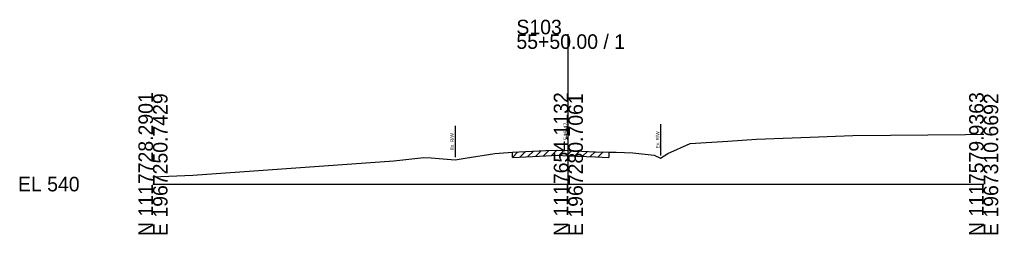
# Model space of a CAD drawing. Extents: x -26 to 163, y -10 to 24018.
# Drawn here: x -25.7 to 162.8, y 4990.3 to 5031.7 of the extents above; entities that cross this region are included whole.
import ezdxf

# ---------------------------------------------------------------- set-up
doc = ezdxf.new("R2010")
doc.units = 0
for name, color, linetype in [('RD_GPK_XS_Cell', 7, 'Continuous'), ('RD_XS_ExGround', 7, 'Continuous'), ('RD_XS_ExPaveRet', 7, 'Continuous'), ('RD_XS_ExRW', 7, 'Continuous'), ('RD_XS_TX_Elev_EX', 7, 'Continuous')]:
    doc.layers.add(name, color=color, linetype=linetype)

msp = doc.modelspace()

# ---------------------------------------------------------------- linework, layer by layer
at = {"layer": 'RD_GPK_XS_Cell'}
for p, q in [((80, 5000), (80, 5028.84)), ((0, 5000), (80, 5000)), ((80, 5000), (160, 5000))]:
    msp.add_line(p, q, dxfattribs=at)
at = {"layer": 'RD_XS_ExGround'}
msp.add_lwpolyline([(0, 5001.42), (7.7, 5001.74), (23.01, 5002.81), (46.41, 5004.49), (52.19, 5005.15), (53.59, 5005.06), (58.18, 5004.69), (60.16, 5005.02), (65.84, 5005.86), (66.67, 5005.94), (69.23, 5006.15), (75.68, 5006.46), (77.87, 5006.56), (80, 5006.47), (85.26, 5006.23), (87.77, 5006.15), (89.22, 5006.12), (92.43, 5005.99), (96.52, 5005.54), (97.78, 5005.01), (99.16, 5005.87), (103.45, 5007.83), (110.74, 5008.28), (116.23, 5008.66), (126.52, 5009.04), (134.83, 5009.36), (156.52, 5009.55), (159.34, 5009.61), (160, 5009.58)], dxfattribs=at)
at = {"layer": 'RD_XS_ExPaveRet'}
for p, q in [((69.23, 5005.15), (70.28, 5006.2)), ((69.23, 5005.15), (69.23, 5006.15)), ((70.73, 5005.22), (71.78, 5006.27)), ((72.23, 5005.29), (73.28, 5006.35)), ((73.73, 5005.37), (74.78, 5006.42)), ((75.23, 5005.44), (76.27, 5006.49)), ((75.68, 5005.46), (77.87, 5005.56)), ((76.73, 5005.51), (77.77, 5006.56)), ((77.87, 5005.56), (80, 5005.47)), ((78.23, 5005.55), (79.18, 5006.5)), ((79.73, 5005.48), (80.68, 5006.44)), ((81.23, 5005.41), (82.18, 5006.37)), ((82.73, 5005.35), (83.68, 5006.3)), ((84.23, 5005.28), (85.18, 5006.24)), ((85.73, 5005.22), (86.69, 5006.19)), ((87.77, 5006.15), (87.77, 5005.15)), ((69.23, 5005.15), (75.68, 5005.46)), ((80, 5005.47), (85.26, 5005.23)), ((85.26, 5005.23), (87.77, 5005.15))]:
    msp.add_line(p, q, dxfattribs=at)
at = {"layer": 'RD_XS_ExRW'}
for p, q in [((97.78, 5011.51), (97.78, 5005.51)), ((58.18, 5011.19), (58.18, 5005.19))]:
    msp.add_line(p, q, dxfattribs=at)

# ---------------------------------------------------------------- texts
at = {"layer": 'RD_GPK_XS_Cell'}
for s, p in [('S103', (70, 5028.84)), ('55+50.00 / 1', (70, 5026.04)), ('EL 540', (-26, 4998.6))]:
    msp.add_text(s, height=2.8, dxfattribs=at).set_placement(p)
for s, p in [('N 1117728.2901', (0, 4990)), ('E 1967250.7429', (2.8, 4990)), ('N 1117654.1132', (80, 4990)), ('E 1967280.7061', (82.8, 4990)), ('N 1117579.9363', (160, 4990)), ('E 1967310.6692', (162.8, 4990))]:
    msp.add_text(s, height=2.8, rotation=90, dxfattribs=at).set_placement(p)
at = {"layer": 'RD_XS_ExRW'}
for p in [(57.93, 5006.53), (97.53, 5006.85)]:
    msp.add_text('Ex. R/W ', height=0.65, rotation=90, dxfattribs=at).set_placement(p)
at = {"layer": 'RD_XS_TX_Elev_EX'}
msp.add_text('546.47', height=0.8, rotation=90, dxfattribs=at).set_placement((79.9, 5008.47))

doc.saveas('drawing.dxf')
